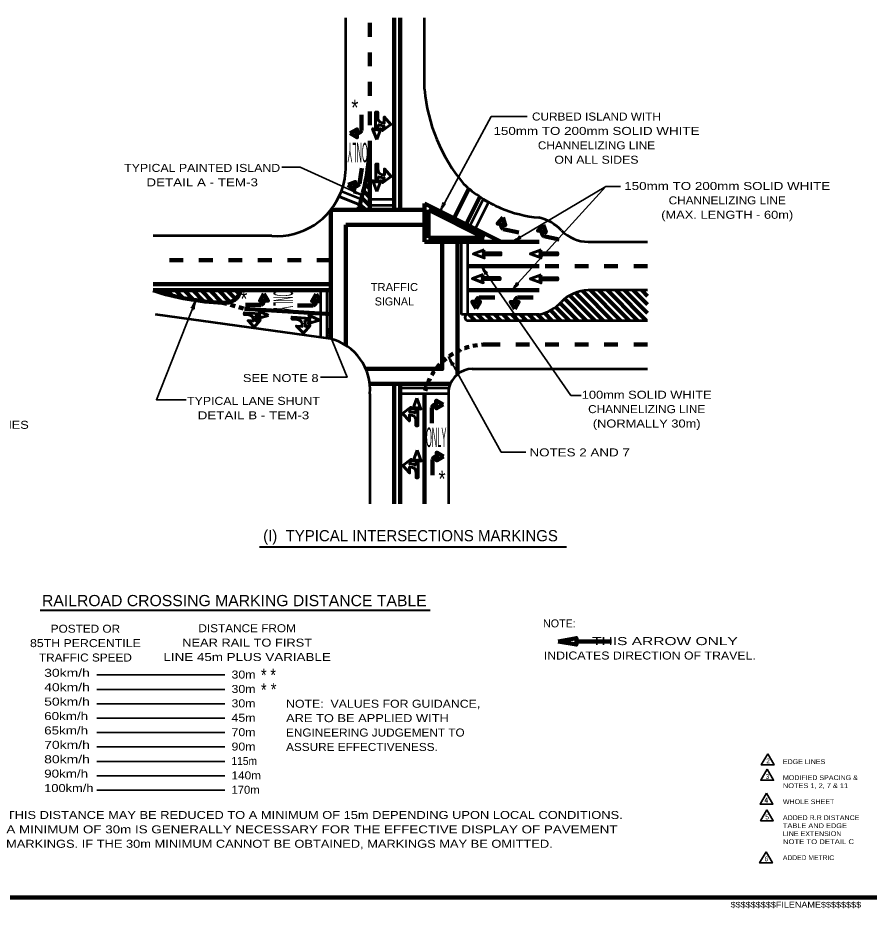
# Model space of a CAD drawing. Extents: x -90 to 765, y -1136 to -592.
# Drawn here: x 218.6 to 537.7, y -1128.2 to -794.4 of the extents above; entities that cross this region are included whole.
import ezdxf
from ezdxf.enums import TextEntityAlignment as Align

# ---------------------------------------------------------------- set-up
doc = ezdxf.new("R2010")
doc.units = 0
doc.header["$LTSCALE"] = 1.2
doc.linetypes.add('SHORT_DASHED', pattern=[2.7, 1.5, -1.2])
doc.layers.add('1', color=7, linetype='Continuous', lineweight=90)

msp = doc.modelspace()

# ---------------------------------------------------------------- linework, layer by layer
at = {"layer": '1', "lineweight": 53}
for p, q in [((341.515, -849.978), (341.515, -794.378)), ((370.992, -821.184), (370.992, -794.378)), ((339.903, -859.318), (347.395, -862.316)), ((339.047, -861.357), (346.777, -864.45)), ((339.047, -861.357), (346.777, -864.45)), ((387.997, -872.509), (392.986, -862.534)), ((313.773, -876.138), (269.367, -876.138)), ((432.397, -878.399), (454.613, -878.399)), ((454.613, -896.55), (432.397, -896.55)), ((335.881, -914.701), (270.271, -905.626)), ((414.001, -905.626), (387.174, -905.626)), ((387.174, -907.837), (454.613, -907.837)), ((334.431, -914.501), (332.22, -914.195)), ((388.91, -925.988), (454.613, -925.988)), ((380.067, -933.124), (380.067, -976.64)), ((380.067, -934.598), (380.067, -935.335)), ((350.591, -935.335), (350.591, -976.64))]:
    msp.add_line(p, q, dxfattribs=at)
at = {"layer": '1'}
for p, q in [((359.666, -866.396), (359.666, -794.378)), ((361.916, -866.396), (361.916, -794.378)), ((350.591, -801.482), (350.591, -796.324)), ((350.591, -812.536), (350.591, -807.378)), ((350.591, -823.59), (350.591, -818.431)), ((350.591, -834.643), (350.591, -829.485)), ((382.143, -869.525), (387.706, -858.404)), ((370.992, -878.375), (370.992, -863.948)), ((399.838, -878.375), (370.992, -863.948)), ((386.65, -871.78), (391.804, -861.474)), ((335.881, -914.701), (335.881, -866.446)), ((346.163, -866.396), (335.921, -866.396)), ((370.992, -866.396), (350.591, -866.396)), ((393.432, -876.863), (372.504, -866.396)), ((372.504, -876.863), (372.504, -866.396)), ((341.515, -917.152), (341.515, -872.03)), ((370.992, -872.03), (341.515, -872.03)), ((393.432, -876.863), (372.504, -876.863)), ((399.838, -878.375), (370.992, -878.375)), ((383.351, -928.091), (383.351, -878.375)), ((399.838, -878.375), (414.001, -878.375)), ((275.454, -885.213), (280.613, -885.213)), ((286.508, -885.213), (291.667, -885.213)), ((297.562, -885.213), (302.72, -885.213)), ((308.615, -885.213), (313.774, -885.213)), ((319.669, -885.213), (324.827, -885.213)), ((330.722, -885.213), (335.881, -885.213)), ((387.174, -887.475), (414.001, -887.475)), ((416.294, -887.475), (421.452, -887.475)), ((427.347, -887.475), (432.506, -887.475)), ((438.401, -887.475), (443.559, -887.475)), ((449.454, -887.475), (454.613, -887.475)), ((335.881, -894.289), (269.367, -894.289)), ((387.174, -896.55), (414.001, -896.55)), ((335.881, -905.463), (303.643, -903.489)), ((394.187, -916.912), (399.345, -916.912)), ((405.24, -916.912), (410.399, -916.912)), ((416.294, -916.912), (421.452, -916.912)), ((427.348, -916.912), (432.506, -916.912)), ((438.401, -916.912), (443.559, -916.912)), ((449.454, -916.912), (454.613, -916.912)), ((350.591, -931.65), (380.679, -931.65)), ((359.666, -931.65), (359.666, -976.64)), ((361.916, -931.65), (361.916, -976.64)), ((370.992, -935.335), (370.992, -976.64)), ((427.963, -1028.169), (441.163, -1028.169))]:
    msp.add_line(p, q, dxfattribs=at)
at = {"layer": '1', "lineweight": 106}
for p, q in [((347.374, -836.615), (347.374, -830.72)), ((350.591, -842.437), (350.51, -842.356)), ((350.591, -845.646), (350.337, -845.392)), ((346.688, -856.594), (347.549, -850.762)), ((350.591, -852.064), (349.698, -851.171)), ((350.591, -848.855), (350.072, -848.336)), ((350.591, -855.272), (349.259, -853.94)), ((350.591, -858.481), (348.759, -856.649)), ((350.591, -861.69), (348.162, -859.261)), ((348.88, -866.396), (346.814, -864.33)), ((350.591, -864.898), (347.51, -861.817)), ((400.58, -873.632), (406.353, -874.828)), ((415.775, -876.283), (421.547, -877.479)), ((272.159, -897.384), (271.325, -896.55)), ((276.529, -898.545), (274.533, -896.55)), ((280.63, -899.438), (277.742, -896.55)), ((284.514, -900.114), (280.951, -896.55)), ((288.218, -900.608), (284.16, -896.55)), ((291.769, -900.951), (287.368, -896.55)), ((295.208, -901.181), (290.577, -896.55)), ((298.172, -900.936), (293.786, -896.55)), ((300.24, -899.796), (296.994, -896.55)), ((301.673, -898.021), (300.203, -896.55)), ((438.065, -907.837), (427.662, -897.434)), ((441.274, -907.837), (430.211, -896.774)), ((444.482, -907.837), (433.196, -896.55)), ((447.691, -907.837), (436.405, -896.55)), ((450.9, -907.837), (439.613, -896.55)), ((454.109, -907.837), (442.822, -896.55)), ((454.613, -905.132), (446.031, -896.55)), ((454.613, -901.923), (449.24, -896.55)), ((454.613, -898.715), (452.448, -896.55)), ((391.5, -899.201), (397.395, -899.195)), ((405.913, -899.3), (411.808, -899.293)), ((428.439, -907.837), (421.927, -901.325)), ((431.648, -907.837), (423.58, -899.769)), ((434.856, -907.837), (425.493, -898.473)), ((309.808, -902.022), (303.913, -902.022)), ((329.315, -902.243), (323.42, -902.243)), ((422.021, -907.837), (418.235, -904.05)), ((425.23, -907.837), (420.189, -902.795)), ((389.934, -907.837), (387.724, -905.626)), ((393.143, -907.837), (390.932, -905.626)), ((396.352, -907.837), (394.141, -905.626)), ((399.561, -907.837), (397.35, -905.626)), ((402.769, -907.837), (400.559, -905.626)), ((405.978, -907.837), (403.767, -905.626)), ((409.187, -907.837), (406.976, -905.626)), ((412.395, -907.837), (410.185, -905.626)), ((415.604, -907.837), (413.393, -905.626)), ((418.813, -907.837), (416.005, -905.029)), ((373.797, -940.436), (373.797, -946.331)), ((374.019, -959.943), (374.019, -965.839))]:
    msp.add_line(p, q, dxfattribs=at)
at = {"layer": '1', "lineweight": 35}
for p, q in [((438.995, -857.684), (403.686, -896.55)), ((438.995, -857.684), (403.982, -878.375)), ((438.995, -857.684), (444.507, -857.684)), ((425.854, -935.969), (392.303, -887.475)), ((399.799, -957.17), (380.034, -921.433)), ((425.854, -935.969), (429.77, -935.969)), ((399.799, -957.17), (409.009, -957.17)), ((248.192, -1040.768), (296.192, -1040.768)), ((248.192, -1046.168), (296.192, -1046.168)), ((248.192, -1051.568), (296.192, -1051.568)), ((248.192, -1056.968), (296.192, -1056.968)), ((248.192, -1062.368), (296.192, -1062.368)), ((248.192, -1067.768), (296.192, -1067.768)), ((248.192, -1073.168), (296.192, -1073.168)), ((248.192, -1078.568), (296.192, -1078.568)), ((248.192, -1083.968), (296.192, -1083.968))]:
    msp.add_line(p, q, dxfattribs=at)
at = {"layer": '1', "linetype": 'SHORT_DASHED'}
msp.add_line((295.261, -901.183), (303.643, -903.489), dxfattribs=at)
at = {"layer": '1', "lineweight": 40}
for p, q in [((309.208, -992.746), (424.305, -992.746)), ((226.95, -1016.444), (373.196, -1016.444))]:
    msp.add_line(p, q, dxfattribs=at)
at = {"layer": '1', "lineweight": 158}
msp.add_line((758.78, -1124.188), (-32.82, -1124.188), dxfattribs=at)
at = {"layer": '1', "lineweight": 60}
for points in [[(352.736, -829.703), (352.736, -836.442), (351.588, -835.982), (353.119, -840.041)], [(353.502, -831.618), (353.502, -829.703), (352.736, -829.703), (352.736, -831.618)], [(353.119, -840.041), (354.651, -835.982), (353.502, -836.442), (353.502, -834.374)], [(354.115, -834.681), (355.876, -834.91), (355.34, -836.672), (358.479, -834.374), (355.952, -831.541), (355.952, -833.762), (354.727, -833.609)], [(352.81, -849.211), (352.81, -855.949), (351.661, -855.49), (353.193, -859.548)], [(353.576, -851.125), (353.576, -849.211), (352.81, -849.211), (352.81, -851.125)], [(354.188, -854.188), (355.95, -854.418), (355.414, -856.179), (358.553, -853.882), (356.026, -851.048), (356.026, -853.269), (354.801, -853.116)], [(353.193, -859.548), (354.725, -855.49), (353.576, -855.949), (353.576, -853.882)], [(393.427, -881.344), (389.369, -882.875), (393.427, -884.407), (392.968, -883.258), (399.706, -883.258), (399.706, -882.493), (397.792, -882.493)], [(399.706, -882.493), (392.968, -882.493), (393.427, -881.344)], [(414.717, -881.344), (410.659, -882.875), (414.717, -884.407), (414.258, -883.258), (420.997, -883.258), (420.997, -882.493), (419.082, -882.493)], [(420.997, -882.493), (414.258, -882.493), (414.717, -881.344)], [(393.074, -890.623), (389.015, -892.154), (393.074, -893.686), (392.614, -892.537), (399.353, -892.537), (399.353, -891.771), (397.439, -891.771)], [(399.353, -891.771), (392.614, -891.771), (393.074, -890.623)], [(414.717, -890.711), (410.659, -892.243), (414.717, -893.774), (414.258, -892.625), (420.997, -892.625), (420.997, -891.86), (419.082, -891.86)], [(420.997, -891.86), (414.258, -891.86), (414.717, -890.711)], [(303.533, -904.991), (309.431, -905.407), (309.1, -904.373), (312.558, -905.964)], [(305.161, -905.779), (303.485, -905.661), (303.533, -904.991), (305.208, -905.109)], [(307.805, -906.505), (307.897, -908.06), (309.472, -907.7), (307.267, -910.306), (304.943, -907.919), (306.887, -908.057), (306.828, -906.975)], [(312.558, -905.964), (308.911, -907.054), (309.384, -906.077), (307.574, -905.949)], [(323.266, -907.501), (321.356, -907.366), (321.41, -906.603), (323.32, -906.737)], [(321.41, -906.603), (328.132, -907.076), (327.755, -905.898), (331.696, -907.711)], [(331.696, -907.711), (327.54, -908.953), (328.079, -907.84), (326.016, -907.695)], [(326.279, -908.327), (326.384, -910.1), (328.178, -909.689), (325.666, -912.66), (323.018, -909.94), (325.233, -910.096), (325.166, -908.863)], [(368.2, -937.01), (366.668, -941.069), (367.817, -940.609), (367.817, -942.677)], [(368.583, -947.348), (368.583, -940.609), (369.731, -941.069), (368.2, -937.01)], [(367.204, -942.37), (365.443, -942.141), (365.979, -940.379), (362.839, -942.677), (365.367, -945.51), (365.367, -943.289), (366.592, -943.442)], [(367.817, -945.433), (367.817, -947.348), (368.583, -947.348), (368.583, -945.433)], [(368.274, -956.518), (366.742, -960.576), (367.891, -960.117), (367.891, -962.184)], [(368.656, -966.855), (368.656, -960.117), (369.805, -960.576), (368.274, -956.518)], [(367.278, -961.878), (365.517, -961.648), (366.053, -959.887), (362.913, -962.184), (365.44, -965.017), (365.44, -962.797), (366.666, -962.95)], [(367.891, -964.941), (367.891, -966.855), (368.656, -966.855), (368.656, -964.941)]]:
    msp.add_lwpolyline(points, dxfattribs=at)
at = {"layer": '1', "lineweight": 35}
for points in [[(376.878, -866.892), (396.042, -831.401), (409.529, -831.401)], [(347.749, -860.994), (324.474, -850.389), (317.552, -850.389)], [(285.363, -900.26), (270.545, -937.596), (281.744, -937.596)], [(334.431, -910.444), (342.055, -929.148), (332.049, -929.148)]]:
    msp.add_lwpolyline(points, dxfattribs=at)
at = {"layer": '1'}
for points in [[(343.177, -837.69), (345.73, -836.216), (345.73, -839.164)], [(342.38, -857.045), (345.12, -855.959), (344.69, -858.875)], [(400.379, -869.305), (401.304, -872.103), (398.418, -871.506)], [(415.574, -871.956), (416.499, -874.754), (413.613, -874.157)], [(310.882, -897.825), (309.409, -900.378), (312.356, -900.378)], [(330.39, -898.046), (328.916, -900.599), (331.864, -900.599)], [(390.43, -903.399), (391.9, -900.845), (388.953, -900.848)], [(404.843, -903.498), (406.314, -900.943), (403.367, -900.946)], [(377.994, -939.361), (375.441, -940.835), (375.441, -937.887)], [(378.216, -958.869), (375.663, -960.342), (375.663, -957.395)], [(421.157, -1028.169), (427.963, -1029.369), (427.963, -1026.969)]]:
    msp.add_lwpolyline(points, close=True, dxfattribs=at)
for points in [[(346.163, -866.396), (350.591, -866.396), (350.591, -840.538)], [(349.053, -926.016), (377.717, -926.016), (377.717, -878.375)], [(335.881, -896.55), (302.261, -896.55), (269.367, -896.55)]]:
    msp.add_lwpolyline(points, dxfattribs=at)
at = {"layer": '1', "lineweight": 53}
for points in [[(346.777, -864.45), (339.047, -861.357), (339.903, -859.318)], [(395.047, -863.469), (390.02, -873.521), (387.997, -872.509)], [(332.22, -914.195), (332.22, -896.55), (334.431, -896.55), (334.431, -914.501)], [(380.067, -935.335), (361.916, -935.335), (361.916, -933.124), (380.191, -933.124)]]:
    msp.add_lwpolyline(points, dxfattribs=at)
for points in [[(359.666, -862.472), (350.591, -862.472), (350.591, -864.682), (359.666, -864.682)], [(384.964, -905.626), (384.964, -878.375), (387.174, -878.375), (387.174, -905.626)]]:
    msp.add_lwpolyline(points, close=True, dxfattribs=at)
at = {"layer": '1', "lineweight": 35}
for points in [[(499.673, -1070.351), (497.273, -1074.508), (502.073, -1074.508)], [(499.476, -1076.066), (497.076, -1080.223), (501.876, -1080.223)], [(499.23, -1085.034), (496.83, -1089.191), (501.63, -1089.191)], [(499.377, -1091.292), (496.978, -1095.449), (501.778, -1095.449)], [(499.04, -1107.065), (496.64, -1111.222), (501.44, -1111.222)]]:
    msp.add_lwpolyline(points, close=True, dxfattribs=at)
at = {"layer": '1', "lineweight": 53}
for centre, radius, start, end in [((435.679, -815.125), 64.971, 185.35014, 219.65818), ((315.633, -850.321), 25.884, 339.65822, 0.75902), ((418.261, -821.886), 47.615, 226.79083, 246.9419), ((315.633, -850.321), 25.884, 265.87745, 339.65822), ((261.443, -838.581), 89.169, 343.13541, 344.5629), ((413.696, -819.658), 47.615, 244.21854, 246.94191), ((418.261, -821.886), 47.615, 246.94191, 264.73353), ((410.573, -885.093), 16.138, 42.83876, 78.14011), ((432.619, -864.079), 14.322, 224.51832, 269.10963), ((432.619, -910.87), 14.322, 90.89037, 135.48168), ((410.573, -889.856), 16.138, 282.26253, 317.16124), ((387.272, -906.731), 1.11, 95.04118, 264.95882), ((330.927, -933.793), 19.724, 355.51724, 75.45459), ((389.261, -935.311), 9.33, 92.15591, 166.44297), ((388.91, -934.598), 8.843, 170.40593, 180)]:
    msp.add_arc(centre, radius, start, end, dxfattribs=at)
at = {"layer": '1', "lineweight": 60}
for centre, radius, start, end in [((355.434, -831.801), 1.941, 174.58762, 248.62739), ((354.456, -833.051), 1.652, 234.73964, 258.17337), ((355.508, -851.308), 1.941, 174.58762, 248.62739), ((354.53, -852.558), 1.652, 234.73964, 258.17337), ((305.202, -907.482), 1.704, 17.34411, 91.38388), ((306.357, -906.703), 1.45, 7.79813, 31.23186), ((323.313, -909.442), 1.941, 17.34411, 91.38388), ((324.629, -908.553), 1.652, 7.79813, 31.23186), ((365.884, -945.25), 1.941, 354.58762, 68.62739), ((366.863, -944), 1.652, 54.73964, 78.17337), ((365.958, -964.758), 1.941, 354.58762, 68.62739), ((366.937, -963.508), 1.652, 54.73964, 78.17337)]:
    msp.add_arc(centre, radius, start, end, dxfattribs=at)
at = {"layer": '1', "lineweight": 106}
for centre, start, end in [((345.873, -836.113), 264.82253, 341.52227), ((345.276, -855.878), 256.43099, 333.13073), ((401.376, -872.264), 163.12105, 239.82079), ((416.57, -874.915), 163.12105, 239.82079), ((309.306, -900.52), 288.47773, 5.17747), ((328.813, -900.742), 288.47773, 5.17747), ((392.003, -900.702), 108.54006, 185.2398), ((406.417, -900.8), 108.54006, 185.2398), ((375.299, -940.937), 84.82253, 161.52227), ((375.52, -960.445), 84.82253, 161.52227)]:
    msp.add_arc(centre, 1.583, start, end, dxfattribs=at)
at = {"layer": '1'}
for centre, radius, start, end in [((261.443, -838.581), 89.169, 343.13541, 358.74229), ((261.443, -838.581), 89.169, 341.8243, 343.13541), ((299.392, -803.419), 97.852, 252.13072, 267.58049), ((296.24, -895.058), 6.203, 260.92323, 346.08365)]:
    msp.add_arc(centre, radius, start, end, dxfattribs=at)
at = {"layer": '1', "linetype": 'SHORT_DASHED'}
msp.add_arc((393.866, -940.322), 23.412, 89.21516, 167.70144, dxfattribs=at)
at = {"layer": '1', "lineweight": 40}
for centre, major_axis, ratio, start_param, end_param in [((346.415, -860.74), (2.028, -0.718), 0.122415, 0.8963533, 3.1415927), ((346.625, -860.192), (1.831, -1.066), 0.07063, 3.1407148, 5.41811), ((377.209, -865.582), (-0.853, -1.975), 0.122415, 0.8963533, 3.1415927), ((377.741, -865.83), (-1.187, -1.755), 0.07063, 3.1407148, 5.41811), ((404.941, -877.424), (-1.749, -1.252), 0.122415, 0.8963533, 3.1415927), ((404.941, -877.424), (-1.749, -1.252), 0.122415, 0.8963533, 3.1415927), ((405.269, -877.91), (-1.922, -0.891), 0.07063, 3.1407148, 5.41811), ((405.269, -877.91), (-1.922, -0.891), 0.07063, 3.1407148, 5.41811), ((392.859, -888.725), (-1.026, 1.853), 0.07063, 3.1407148, 5.41811), ((393.321, -888.363), (-1.373, 1.656), 0.122415, 0.8963533, 3.1415927), ((404.321, -895.358), (-1.302, -1.712), 0.122415, 0.8963533, 3.1415927), ((404.778, -895.726), (-1.573, -1.418), 0.07063, 3.1407148, 5.41811), ((284.631, -901.416), (0.973, 1.881), 0.07063, 3.1407148, 5.41811), ((285.189, -901.599), (0.616, 2.061), 0.122415, 0.8963533, 3.1415927), ((334.703, -911.785), (-0.6, 2.031), 0.07063, 3.1407148, 5.41811), ((335.232, -911.531), (-0.982, 1.914), 0.122415, 0.8963533, 3.1415927), ((380.463, -922.732), (-0.836, 1.946), 0.07063, 3.1407148, 5.41811), ((380.958, -922.418), (-1.201, 1.784), 0.122415, 0.8963533, 3.1415927)]:
    msp.add_ellipse(centre, major_axis=major_axis, ratio=ratio, start_param=start_param, end_param=end_param, dxfattribs=at)

# ---------------------------------------------------------------- texts
at = {"layer": '1'}
for s, height, width, p in [('*', 6, 0.85, (343.616, -831.016)), ('*', 6, 0.85, (302.031, -902.733)), ('SEE NOTE 8', 3, 1.2, (302.984, -930.936)), ('100mm SOLID YELLOW BARRIER LINES', 3, 1.2, (131.502, -948.481)), ('NOTES 2 AND 7', 3, 1.25, (410.386, -958.818)), ('*', 6, 0.85, (376.296, -970.226)), ('RAILROAD CROSSING MARKING DISTANCE TABLE', 4.2, 1.05, (227.686, -1014.973)), ('30km/h', 3, 1.3, (228.508, -1041.464)), ('30m', 3, 1.15, (298.717, -1042.116)), ('40km/h', 3, 1.3, (228.508, -1046.864)), ('30m', 3, 1.15, (298.717, -1047.515)), ('50km/h', 3, 1.3, (228.508, -1052.264)), ('30m', 3, 1.15, (298.717, -1052.916)), ('NOTE:  VALUES FOR GUIDANCE,', 3, 1.15, (319.156, -1053.053)), ('60km/h', 3, 1.25, (228.508, -1057.664)), ('45m', 3, 1.15, (298.717, -1058.316)), ('ARE TO BE APPLIED WITH', 3, 1.2, (319.156, -1058.453)), ('65km/h', 3, 1.25, (228.508, -1063.064)), ('70m', 3, 1.15, (298.717, -1063.716)), ('ENGINEERING JUDGEMENT TO', 3, 1.1, (319.156, -1063.853)), ('70km/h', 3, 1.3, (228.508, -1068.464)), ('90m', 3, 1.15, (298.717, -1069.116)), ('ASSURE EFFECTIVENESS.', 3, 1.1, (319.156, -1069.253)), ('80km/h', 3, 1.3, (228.508, -1073.864)), ('115m', 3, 0.95, (298.717, -1074.515)), ('2', 1.8, 0.9, (499.112, -1073.904)), ('EDGE LINES', 1.8, 1.1, (505.367, -1074.177)), ('90km/h', 3, 1.25, (228.508, -1079.264)), ('140m', 3, 1.1, (298.717, -1079.916)), ('3', 1.8, 0.9, (498.865, -1079.718)), ('100km/h', 3, 1.2, (228.508, -1084.664)), ('MODIFIED SPACING &', 1.8, 1.1, (505.367, -1080.177)), ('NOTES 1, 2, 7 & 11', 1.8, 1.15, (505.367, -1083.177)), ('170m', 3, 1.05, (298.717, -1085.316)), ('4', 1.8, 0.95, (498.422, -1088.538)), ('4', 1.8, 0.95, (498.422, -1088.735)), ('WHOLE SHEET', 1.8, 1.1, (505.367, -1089.177)), ('- THIS DISTANCE MAY BE REDUCED TO A MINIMUM OF 15m DEPENDING UPON LOCAL CONDITIONS.', 3, 1.2, (211.554, -1094.758)), ('5', 1.8, 0.9, (498.767, -1094.894)), ('ADDED R.R DISTANCE', 1.8, 1.1, (505.367, -1095.177)), ('  A MINIMUM OF 30m IS GENERALLY NECESSARY FOR THE EFFECTIVE DISPLAY OF PAVEMENT', 3, 1.25, (211.554, -1100.158)), ('TABLE AND EDGE', 1.8, 1.15, (505.367, -1098.177)), ('LINE EXTENSION', 1.8, 1.1, (505.367, -1101.177)), ('  MARKINGS. IF THE 30m MINIMUM CANNOT BE OBTAINED, MARKINGS MAY BE OMITTED.', 3, 1.2, (211.554, -1105.558)), ('NOTE TO DETAIL C', 1.8, 1.2, (505.367, -1104.177)), ('6', 1.8, 0.85, (498.479, -1110.619)), ('ADDED METRIC', 1.8, 1.05, (505.367, -1110.177)), ('$$$$$$$$$FILENAME$$$$$$$$', 2.2, 1.15, (485.78, -1127.988))]:
    msp.add_text(s, height=height, dxfattribs=dict(at, width=width)).set_placement(p)
for s, height, width, p in [('CURBED ISLAND WITH', 3, 1.1, (435.491, -832.89)), ('150mm TO 200mm SOLID WHITE', 3, 1.25, (435.491, -838.29)), ('CHANNELIZING LINE', 3, 1.1, (435.491, -843.69)), ('ON ALL SIDES', 3, 1.15, (435.491, -849.09)), ('TYPICAL PAINTED ISLAND', 3, 1.15, (287.722, -852.156)), ('DETAIL A - TEM-3', 3, 1.25, (287.722, -857.556)), ('150mm TO 200mm SOLID WHITE', 3, 1.25, (484.5, -858.926)), ('CHANNELIZING LINE', 3, 1.1, (484.5, -864.326)), ('(MAX. LENGTH - 60m)', 3, 1.2, (484.5, -869.726)), ('TRAFFIC', 3, 1.05, (359.748, -896.823)), ('100mm SOLID WHITE', 3, 1.2, (454.323, -937.197)), ('TYPICAL LANE SHUNT', 3, 1.15, (306.939, -939.51)), ('CHANNELIZING LINE', 3, 1.1, (454.323, -942.597)), ('DETAIL B - TEM-3', 3, 1.25, (306.939, -944.91)), ('ONLY', 7.321, 0.25, (375.441, -955.326)), ('(NORMALLY 30m)', 3, 1.2, (454.323, -947.997)), ('POSTED OR', 3, 1.1, (243.958, -1024.924)), ('DISTANCE FROM', 3, 1.1, (304.573, -1024.741)), ('85TH PERCENTILE', 3, 1.15, (243.957, -1030.324)), ('NEAR RAIL TO FIRST', 3, 1.2, (304.573, -1030.141)), ('       THIS ARROW ONLY', 3, 1.45, (455.494, -1029.571)), ('TRAFFIC SPEED', 3, 1.1, (243.957, -1035.724)), ('LINE 45m PLUS VARIABLE', 3, 1.25, (304.573, -1035.541)), ('INDICATES DIRECTION OF TRAVEL.', 3, 1.15, (455.494, -1034.971)), ('*', 4.8, 0.85, (310.809, -1043.21)), ('*', 4.8, 0.85, (314.32, -1043.21)), ('*', 4.8, 0.85, (310.81, -1048.739)), ('*', 4.8, 0.85, (314.499, -1048.561))]:
    msp.add_text(s, height=height, dxfattribs=dict(at, width=width)).set_placement(p, align=Align.CENTER)
at = {"layer": '1', "width": 0.25}
for rotation, p in [(180, (345.952, -841.232)), (270, (314.425, -900.433))]:
    msp.add_text('ONLY', height=7.321, rotation=rotation, dxfattribs=at).set_placement(p, align=Align.CENTER)
at = {"layer": '1'}
for s, p in [('SIGNAL', (359.748, -902.223)), ('NOTE:', (421.6, -1022.932))]:
    msp.add_text(s, height=3, dxfattribs=at).set_placement(p, align=Align.CENTER)
msp.add_text('(I)  TYPICAL INTERSECTIONS MARKINGS', height=4.2, dxfattribs=at).set_placement((310.574, -990.644))

doc.saveas('drawing.dxf')
